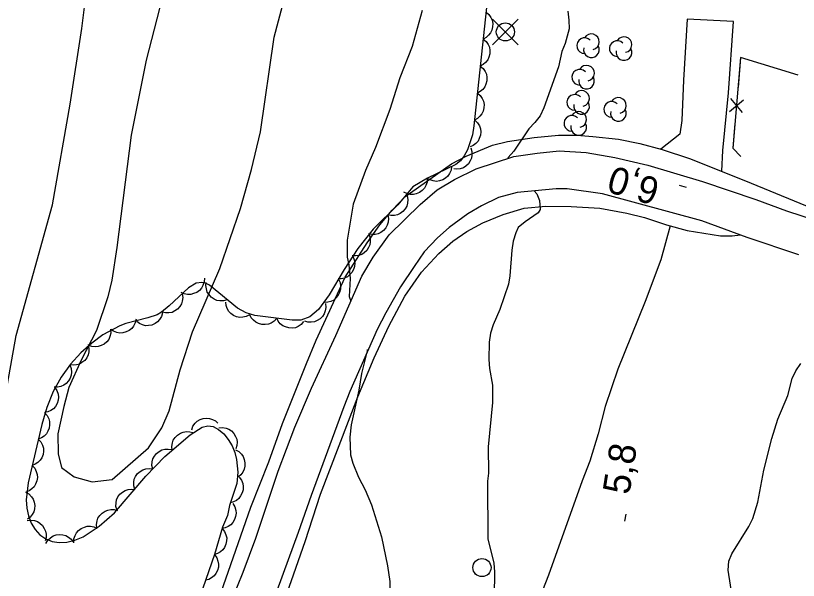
# Model space of a CAD drawing. Extents: x 282461 to 284471, y 5554090 to 5557646.
# Drawn here: x 283430.5 to 283517.1, y 5554920.6 to 5554983 of the extents above; entities that cross this region are included whole.
import ezdxf

# ---------------------------------------------------------------- set-up
doc = ezdxf.new("R2010")
doc.units = 0
for name, color, linetype in [('Niveau 1', 7, 'Continuous'), ('Niveau 19', 7, 'Continuous'), ('Niveau 2', 7, 'Continuous'), ('Niveau 21', 7, 'Continuous'), ('Niveau 22', 7, 'Continuous'), ('Niveau 3', 7, 'Continuous'), ('Niveau 36', 7, 'Continuous'), ('Niveau 37', 7, 'Continuous'), ('Niveau 44', 7, 'Continuous')]:
    doc.layers.add(name, color=color, linetype=linetype)

msp = doc.modelspace()

# ---------------------------------------------------------------- linework, layer by layer
at = {"layer": 'Niveau 1'}
for points in [[(283491.56, 5554983.49), (283491.69, 5554982.5), (283491.7, 5554981.52), (283491.26, 5554979.89), (283490.92, 5554979.02), (283490.53, 5554977.33), (283488.9, 5554972.8), (283488.5, 5554971.92), (283487.93, 5554971.17), (283487.24, 5554970.46), (283485.59, 5554968.01), (283484.96, 5554967.31), (283484.88, 5554967.16)], [(283487.85, 5554963.62), (283488.14, 5554963.29), (283488.44, 5554962.54), (283488.51, 5554961.55), (283488.28, 5554961.2), (283486.84, 5554960.2), (283486.09, 5554959.56), (283485.81, 5554958.98), (283485.53, 5554958.05), (283485.37, 5554957.06), (283485.17, 5554954.22), (283485, 5554953.29), (283484.05, 5554950.5), (283483.31, 5554948.81), (283483.03, 5554947.88), (283482.87, 5554946.9), (283482.83, 5554944.98), (283482.9, 5554944), (283483.22, 5554942.15), (283483.24, 5554940.24), (283482.77, 5554935.31), (283482.81, 5554932.41), (283482.7, 5554931.54), (283482.72, 5554925.17), (283483.39, 5554922.45), (283483.46, 5554921.52), (283483.43, 5554918.8)], [(283509.74, 5554918.86), (283509.3, 5554921.7), (283509.35, 5554922.68), (283509.68, 5554923.5), (283511.57, 5554926.53), (283512.02, 5554927.4), (283512.58, 5554929.2), (283513.24, 5554932.74), (283514.13, 5554936.23), (283514.8, 5554938.38), (283515.87, 5554941), (283516.37, 5554942.86), (283516.77, 5554943.73), (283517.34, 5554944.54)]]:
    msp.add_lwpolyline(points, dxfattribs=at)
at = {"layer": 'Niveau 19'}
msp.add_lwpolyline([(283508.58, 5554965.8), (283508.69, 5554968.08), (283509.33, 5554974.46), (283509.88, 5554982.34), (283504.77, 5554982.58), (283504.36, 5554975.86), (283504.18, 5554971.4), (283503.94, 5554969.89), (283501.86, 5554968.21)], dxfattribs=at)
at = {"layer": 'Niveau 2'}
for points in [[(283428.84, 5554937.89), (283430.58, 5554947.64), (283434.6, 5554962.06), (283436.56, 5554973.21), (283437.85, 5554981.57), (283438.49, 5554986.91), (283440.02, 5554994.58), (283441.12, 5555000.62), (283444.68, 5555013.88), (283446.71, 5555019.23), (283450.1, 5555026.92), (283452.13, 5555032.74), (283455.26, 5555043.44), (283455.92, 5555046.46), (283458.16, 5555053.68), (283461.99, 5555064.39)], [(283449.39, 5554995.38), (283444.94, 5554978.05), (283443.29, 5554969.79), (283441.69, 5554957.36), (283441.15, 5554953.75), (283440.71, 5554951.89), (283439.47, 5554948.17), (283437.77, 5554944.9)], [(283437.77, 5554944.9), (283436.41, 5554941.87), (283435.85, 5554939.78), (283435.19, 5554936.76), (283435.21, 5554934.55), (283435.58, 5554933.05), (283436.99, 5554932.01), (283438.97, 5554931.45), (283441.18, 5554931.7), (283445.21, 5554935.22), (283446.69, 5554937.44), (283447.48, 5554939.3), (283448.71, 5554943.84), (283450.06, 5554948.03), (283453.11, 5554955.02), (283455.36, 5554961.66), (283456.59, 5554965.97), (283457.59, 5554970.15), (283459.1, 5554980.61), (283460.21, 5554984.8)], [(283475.48, 5554983.55), (283474.37, 5554979.59), (283473.01, 5554976.1), (283471.89, 5554972.61), (283470.31, 5554968.42), (283469.18, 5554965.86), (283467.83, 5554962.13), (283467.18, 5554958.18), (283467.17, 5554956.3), (283467.36, 5554955.43), (283467.49, 5554953.92), (283467.4, 5554951.95), (283467.58, 5554951.44)], [(283469.37, 5554946.09), (283469.38, 5554945.94), (283468.77, 5554943.44), (283468.45, 5554941.58), (283467.62, 5554937.75), (283467.46, 5554936.41), (283467.54, 5554934.44), (283467.79, 5554933.52), (283468.44, 5554931.96), (283469.16, 5554930.57), (283469.87, 5554928.9), (283470.96, 5554925.37), (283471.64, 5554922.18), (283471.89, 5554920.45), (283471.92, 5554918.19), (283471.6, 5554915.28), (283470.94, 5554912.21), (283470.8, 5554910.14)]]:
    msp.add_lwpolyline(points, dxfattribs=at)
at = {"layer": 'Niveau 21'}
for points in [[(283451.28, 5554913.64), (283456.53, 5554928.64), (283458.5, 5554933.65), (283460.02, 5554937.89), (283462.67, 5554944.53), (283463.75, 5554947.12), (283466.96, 5554954.08), (283469.39, 5554957.87), (283470.78, 5554959.86), (283472.14, 5554961.5), (283473.53, 5554962.94), (283478.69, 5554966.62), (283480.32, 5554967.45), (283483.24, 5554968.67), (283484.91, 5554969.09), (283487.84, 5554969.5), (283490.52, 5554969.76), (283492.56, 5554969.76), (283494.33, 5554969.63), (283497.18, 5554969.34), (283499.51, 5554968.85), (283502, 5554968.18), (283505.02, 5554967.2), (283511.22, 5554964.73), (283519.9, 5554961.14)], [(283454.42, 5554918.36), (283455.68, 5554921.48), (283457.06, 5554925.23), (283459.56, 5554932.65), (283461.39, 5554937.51), (283463.23, 5554941.79), (283465.9, 5554947.63), (283468.78, 5554954.19), (283470.06, 5554956.29), (283471.83, 5554958.77), (283475.24, 5554962.12), (283477.11, 5554963.73), (283479.03, 5554964.88), (283481.44, 5554966.04), (283485.61, 5554967.4), (283488.19, 5554967.8), (283490.59, 5554968.03), (283493.61, 5554967.86), (283496.77, 5554967.29), (283500.4, 5554966.46), (283506.44, 5554964.64), (283512.36, 5554962.66), (283515.73, 5554961.41), (283529.41, 5554956.95)], [(283517.11, 5554956.53), (283511.41, 5554958.48), (283506.39, 5554960.32), (283495.39, 5554963.28), (283491.48, 5554963.84), (283490.29, 5554963.85), (283485.96, 5554963.45), (283483.89, 5554962.9), (283482.01, 5554961.98), (283480.52, 5554961.09), (283478.46, 5554959.56), (283477.15, 5554958.42), (283475.69, 5554956.89), (283474.56, 5554955.26), (283473.06, 5554953.01), (283471.44, 5554950.15), (283470.49, 5554948.29), (283467.46, 5554941.44), (283466.81, 5554939.73), (283463.18, 5554929.95), (283461.77, 5554925.85), (283458.29, 5554916.39)], [(283456.73, 5554908.34), (283462.54, 5554924.87), (283464.22, 5554930.1), (283468.35, 5554940.84), (283470.16, 5554945.15), (283471.76, 5554948.65), (283473.53, 5554951.97), (283475.4, 5554954.63), (283477.31, 5554956.68), (283478.85, 5554958.06), (283480.39, 5554959.12), (283482.18, 5554960.09), (283484.43, 5554961.02), (283486.75, 5554961.71), (283489.14, 5554961.94), (283491.93, 5554961.9), (283495.1, 5554961.7), (283498.09, 5554961.16), (283500.05, 5554960.69), (283502.47, 5554959.87), (283504.77, 5554959.23), (283508.43, 5554958.65), (283509.74, 5554958.64), (283510.66, 5554958.77)]]:
    msp.add_lwpolyline(points, dxfattribs=at)
at = {"layer": 'Niveau 22'}
msp.add_lwpolyline([(283502.87, 5554959.76), (283501.86, 5554955.98), (283500.11, 5554951.39), (283497.09, 5554943.9), (283495.69, 5554939.77), (283494.91, 5554936.75), (283493.99, 5554933.73), (283493.15, 5554931.58), (283489.44, 5554921.14), (283487.04, 5554915.03), (283485.83, 5554912.28), (283483.49, 5554905.88), (283481.09, 5554899.64), (283477.06, 5554887.26), (283475.82, 5554884.03)], dxfattribs=at)
at = {"layer": 'Niveau 3'}
for p, q in [((283504.67, 5554963.99), (283503.9, 5554964.22)), ((283497.88, 5554927.1), (283498, 5554927.89))]:
    msp.add_line(p, q, dxfattribs=at)
at = {"layer": 'Niveau 36'}
for p, q in [((283486.06, 5554979.77), (283483.24, 5554982.59)), ((283483.24, 5554979.77), (283486.06, 5554982.59))]:
    msp.add_line(p, q, dxfattribs=at)
for centre in [(283484.659, 5554981.191), (283482.075, 5554921.973)]:
    msp.add_circle(centre, 1, dxfattribs=at)
at = {"layer": 'Niveau 37'}
for p, q in [((283509.44, 5554972.39), (283510.97, 5554973.68)), ((283509.56, 5554973.81), (283510.85, 5554972.27))]:
    msp.add_line(p, q, dxfattribs=at)
for points in [[(283517.02, 5554976.4), (283510.67, 5554978.37), (283509.8, 5554968.35), (283510.68, 5554967.43)], [(283517.02, 5554976.4), (283510.67, 5554978.37), (283510.38, 5554975.03)], [(283510.03, 5554971.05), (283509.8, 5554968.35), (283510.68, 5554967.43)]]:
    msp.add_lwpolyline(points, dxfattribs=at)
at = {"layer": 'Niveau 44'}
for points in [[(283482.65, 5554984.58), (283481.18, 5554970.8), (283481.01, 5554969.81), (283480.48, 5554968.15), (283480.12, 5554967.48), (283479.69, 5554966.95), (283479.19, 5554966.54), (283476.05, 5554965.01), (283474.44, 5554964.05), (283472.77, 5554962.06), (283470.05, 5554959.37), (283468.34, 5554957.23), (283466.84, 5554954.93), (283465.18, 5554952.14), (283463.99, 5554950.49), (283463.05, 5554949.69), (283462.03, 5554949.33), (283461.09, 5554949.32), (283456.98, 5554949.85), (283456, 5554950.13), (283455.03, 5554950.64), (283451.95, 5554953.2), (283451.51, 5554953.4), (283451.11, 5554953.48), (283450.46, 5554953.4), (283449.64, 5554952.9), (283447.5, 5554950.92), (283446.63, 5554950.21), (283446.15, 5554949.93), (283445.13, 5554949.58), (283442.7, 5554948.97), (283442.05, 5554948.71), (283440.17, 5554947.69), (283438.93, 5554946.78), (283437.71, 5554945.72), (283436.57, 5554944.46), (283435.57, 5554943.04), (283434.67, 5554941.43), (283433.96, 5554939.66), (283433.4, 5554937.8), (283431.9, 5554931.36), (283431.68, 5554929.47), (283431.75, 5554928.55), (283431.94, 5554927.68), (283432.25, 5554926.89), (283432.68, 5554926.18), (283433.21, 5554925.59), (283433.84, 5554925.14), (283434.56, 5554924.85), (283435.34, 5554924.73), (283436.19, 5554924.78), (283437.07, 5554924.99), (283437.98, 5554925.38), (283439.77, 5554926.54), (283441.46, 5554928.02), (283444.93, 5554932.07), (283447.03, 5554934.27), (283449.83, 5554936.65), (283451.14, 5554937.5), (283451.78, 5554937.66), (283452.37, 5554937.56), (283452.96, 5554937.25), (283453.52, 5554936.77), (283454.03, 5554936.15), (283454.44, 5554935.45), (283454.74, 5554934.7), (283454.93, 5554933.92), (283455.08, 5554932.54), (283454.98, 5554931.26), (283454.15, 5554928.84), (283453.94, 5554927.72), (283453.38, 5554926.43), (283452.5, 5554923.42), (283451.21, 5554919.71)], [(283482.52, 5554983.38), (283482.84, 5554983.11), (283483.06, 5554982.77), (283483.2, 5554982.47), (283483.26, 5554982.12), (283483.25, 5554981.75), (283483.15, 5554981.38), (283483.03, 5554981.08), (283482.8, 5554980.81), (283482.52, 5554980.56), (283482.2, 5554980.4)], [(283482.2, 5554980.4), (283482.52, 5554980.13), (283482.74, 5554979.78), (283482.89, 5554979.49), (283482.94, 5554979.14), (283482.93, 5554978.77), (283482.83, 5554978.4), (283482.71, 5554978.1), (283482.48, 5554977.82), (283482.2, 5554977.58), (283481.89, 5554977.41)], [(283481.89, 5554977.41), (283482.2, 5554977.14), (283482.43, 5554976.8), (283482.57, 5554976.5), (283482.62, 5554976.15), (283482.61, 5554975.78), (283482.51, 5554975.41), (283482.39, 5554975.11), (283482.16, 5554974.84), (283481.88, 5554974.6), (283481.57, 5554974.43)], [(283481.57, 5554974.43), (283481.89, 5554974.16), (283482.11, 5554973.82), (283482.25, 5554973.52), (283482.3, 5554973.17), (283482.29, 5554972.8), (283482.19, 5554972.43), (283482.07, 5554972.13), (283481.85, 5554971.86), (283481.57, 5554971.61), (283481.25, 5554971.44)], [(283481.29, 5554971.44), (283481.59, 5554971.15), (283481.79, 5554970.79), (283481.91, 5554970.48), (283481.94, 5554970.13), (283481.91, 5554969.77), (283481.78, 5554969.4), (283481.64, 5554969.11), (283481.4, 5554968.85), (283481.11, 5554968.63), (283480.78, 5554968.48)], [(283480.85, 5554968.37), (283480.97, 5554967.97), (283480.97, 5554967.57), (283480.92, 5554967.24), (283480.78, 5554966.92), (283480.57, 5554966.61), (283480.28, 5554966.36), (283480.02, 5554966.17), (283479.68, 5554966.07), (283479.31, 5554966.01), (283478.95, 5554966.04)], [(283478.72, 5554966.31), (283478.66, 5554965.9), (283478.49, 5554965.53), (283478.31, 5554965.25), (283478.05, 5554965.02), (283477.73, 5554964.83), (283477.36, 5554964.72), (283477.04, 5554964.66), (283476.69, 5554964.71), (283476.34, 5554964.82), (283476.02, 5554965)], [(283476.03, 5554965), (283476, 5554964.58), (283475.86, 5554964.2), (283475.71, 5554963.9), (283475.46, 5554963.65), (283475.16, 5554963.44), (283474.8, 5554963.3), (283474.49, 5554963.21), (283474.14, 5554963.23), (283473.77, 5554963.31), (283473.45, 5554963.46)], [(283473.8, 5554963.07), (283473.87, 5554962.66), (283473.83, 5554962.26), (283473.75, 5554961.94), (283473.57, 5554961.64), (283473.33, 5554961.35), (283473.02, 5554961.13), (283472.73, 5554960.97), (283472.39, 5554960.91), (283472.01, 5554960.89), (283471.66, 5554960.96)], [(283471.66, 5554960.96), (283471.74, 5554960.55), (283471.69, 5554960.15), (283471.61, 5554959.83), (283471.44, 5554959.52), (283471.2, 5554959.24), (283470.88, 5554959.02), (283470.6, 5554958.86), (283470.25, 5554958.8), (283469.88, 5554958.78), (283469.53, 5554958.85)], [(283469.59, 5554958.8), (283469.72, 5554958.4), (283469.72, 5554957.99), (283469.68, 5554957.66), (283469.53, 5554957.34), (283469.33, 5554957.03), (283469.04, 5554956.78), (283468.78, 5554956.59), (283468.44, 5554956.48), (283468.08, 5554956.42), (283467.72, 5554956.45)], [(283467.8, 5554956.39), (283467.96, 5554956.01), (283468, 5554955.61), (283467.99, 5554955.27), (283467.88, 5554954.94), (283467.7, 5554954.61), (283467.44, 5554954.33), (283467.2, 5554954.12), (283466.88, 5554953.98), (283466.52, 5554953.89), (283466.16, 5554953.88)], [(283451.39, 5554953.97), (283451.37, 5554953.55), (283451.23, 5554953.17), (283451.08, 5554952.87), (283450.84, 5554952.62), (283450.54, 5554952.4), (283450.18, 5554952.26), (283449.87, 5554952.17), (283449.52, 5554952.18), (283449.15, 5554952.25), (283448.83, 5554952.4)], [(283453.9, 5554951.58), (283453.5, 5554951.46), (283453.1, 5554951.46), (283452.77, 5554951.51), (283452.45, 5554951.66), (283452.15, 5554951.87), (283451.9, 5554952.16), (283451.71, 5554952.43), (283451.61, 5554952.77), (283451.56, 5554953.14), (283451.6, 5554953.49)], [(283466.2, 5554953.85), (283466.38, 5554953.48), (283466.44, 5554953.07), (283466.44, 5554952.74), (283466.34, 5554952.4), (283466.18, 5554952.07), (283465.93, 5554951.78), (283465.7, 5554951.55), (283465.38, 5554951.4), (283465.02, 5554951.3), (283464.66, 5554951.27)], [(283448.94, 5554952.25), (283449, 5554951.84), (283448.94, 5554951.44), (283448.85, 5554951.12), (283448.67, 5554950.82), (283448.42, 5554950.55), (283448.1, 5554950.34), (283447.81, 5554950.19), (283447.46, 5554950.13), (283447.09, 5554950.13), (283446.74, 5554950.21)], [(283456.39, 5554949.92), (283456.02, 5554949.73), (283455.62, 5554949.65), (283455.29, 5554949.63), (283454.95, 5554949.7), (283454.61, 5554949.85), (283454.31, 5554950.08), (283454.07, 5554950.3), (283453.9, 5554950.61), (283453.78, 5554950.96), (283453.74, 5554951.32)], [(283464.77, 5554951.16), (283464.82, 5554950.74), (283464.74, 5554950.34), (283464.64, 5554950.03), (283464.44, 5554949.74), (283464.18, 5554949.47), (283463.85, 5554949.28), (283463.55, 5554949.14), (283463.2, 5554949.1), (283462.83, 5554949.11), (283462.49, 5554949.21)], [(283446.75, 5554950.14), (283446.64, 5554949.73), (283446.43, 5554949.39), (283446.22, 5554949.13), (283445.93, 5554948.94), (283445.59, 5554948.79), (283445.21, 5554948.73), (283444.88, 5554948.71), (283444.54, 5554948.8), (283444.2, 5554948.95), (283443.92, 5554949.16)], [(283443.83, 5554949.42), (283443.74, 5554949.02), (283443.55, 5554948.66), (283443.35, 5554948.4), (283443.07, 5554948.19), (283442.74, 5554948.02), (283442.36, 5554947.94), (283442.04, 5554947.9), (283441.69, 5554947.97), (283441.35, 5554948.11), (283441.05, 5554948.31)], [(283459.38, 5554949.54), (283459.11, 5554949.23), (283458.76, 5554949.01), (283458.46, 5554948.88), (283458.11, 5554948.83), (283457.74, 5554948.85), (283457.38, 5554948.96), (283457.07, 5554949.09), (283456.81, 5554949.32), (283456.57, 5554949.6), (283456.41, 5554949.92)], [(283462.36, 5554949.16), (283462.08, 5554948.84), (283461.74, 5554948.63), (283461.44, 5554948.49), (283461.09, 5554948.45), (283460.72, 5554948.46), (283460.35, 5554948.58), (283460.05, 5554948.7), (283459.78, 5554948.93), (283459.55, 5554949.22), (283459.38, 5554949.54)], [(283441.02, 5554948.32), (283441.04, 5554947.9), (283440.94, 5554947.51), (283440.81, 5554947.2), (283440.59, 5554946.93), (283440.31, 5554946.68), (283439.97, 5554946.51), (283439.66, 5554946.4), (283439.31, 5554946.38), (283438.94, 5554946.42), (283438.6, 5554946.54)], [(283438.52, 5554946.62), (283438.62, 5554946.21), (283438.6, 5554945.81), (283438.54, 5554945.48), (283438.38, 5554945.17), (283438.15, 5554944.87), (283437.85, 5554944.64), (283437.58, 5554944.46), (283437.24, 5554944.38), (283436.87, 5554944.34), (283436.51, 5554944.39)], [(283436.52, 5554944.39), (283436.67, 5554944), (283436.69, 5554943.59), (283436.67, 5554943.26), (283436.55, 5554942.93), (283436.36, 5554942.61), (283436.09, 5554942.34), (283435.84, 5554942.13), (283435.51, 5554942), (283435.15, 5554941.93), (283434.79, 5554941.93)], [(283434.85, 5554941.88), (283435.09, 5554941.54), (283435.21, 5554941.15), (283435.26, 5554940.82), (283435.22, 5554940.47), (283435.11, 5554940.12), (283434.91, 5554939.79), (283434.71, 5554939.53), (283434.42, 5554939.33), (283434.09, 5554939.18), (283433.73, 5554939.1)], [(283433.7, 5554939.1), (283433.99, 5554938.8), (283434.17, 5554938.43), (283434.27, 5554938.12), (283434.28, 5554937.76), (283434.23, 5554937.4), (283434.08, 5554937.05), (283433.92, 5554936.76), (283433.67, 5554936.52), (283433.36, 5554936.31), (283433.02, 5554936.18)], [(283449.98, 5554937.21), (283450.12, 5554937.6), (283450.37, 5554937.93), (283450.6, 5554938.16), (283450.91, 5554938.33), (283451.26, 5554938.45), (283451.64, 5554938.48), (283451.96, 5554938.47), (283452.3, 5554938.36), (283452.62, 5554938.18), (283452.89, 5554937.94)], [(283447.82, 5554934.94), (283447.77, 5554935.36), (283447.85, 5554935.76), (283447.95, 5554936.07), (283448.15, 5554936.36), (283448.41, 5554936.62), (283448.74, 5554936.82), (283449.04, 5554936.96), (283449.39, 5554937), (283449.76, 5554936.98), (283450.11, 5554936.89)], [(283452.97, 5554937.43), (283453.39, 5554937.47), (283453.79, 5554937.39), (283454.1, 5554937.28), (283454.39, 5554937.08), (283454.65, 5554936.81), (283454.84, 5554936.48), (283454.97, 5554936.18), (283455, 5554935.83), (283454.98, 5554935.46), (283454.88, 5554935.12)], [(283433.02, 5554936.18), (283433.31, 5554935.87), (283433.48, 5554935.51), (283433.59, 5554935.19), (283433.6, 5554934.84), (283433.55, 5554934.48), (283433.4, 5554934.12), (283433.24, 5554933.84), (283432.99, 5554933.59), (283432.68, 5554933.39), (283432.34, 5554933.26)], [(283445.67, 5554932.85), (283445.59, 5554933.26), (283445.62, 5554933.66), (283445.69, 5554933.99), (283445.86, 5554934.29), (283446.09, 5554934.58), (283446.4, 5554934.81), (283446.68, 5554934.98), (283447.02, 5554935.06), (283447.39, 5554935.08), (283447.75, 5554935.02)], [(283454.81, 5554935), (283455.18, 5554934.8), (283455.47, 5554934.51), (283455.67, 5554934.25), (283455.8, 5554933.92), (283455.87, 5554933.56), (283455.85, 5554933.18), (283455.79, 5554932.86), (283455.63, 5554932.54), (283455.41, 5554932.24), (283455.14, 5554932.01)], [(283432.34, 5554933.26), (283432.63, 5554932.95), (283432.8, 5554932.58), (283432.91, 5554932.27), (283432.92, 5554931.92), (283432.87, 5554931.55), (283432.72, 5554931.2), (283432.56, 5554930.91), (283432.3, 5554930.67), (283432, 5554930.46), (283431.66, 5554930.33)], [(283443.68, 5554930.61), (283443.57, 5554931.01), (283443.58, 5554931.42), (283443.63, 5554931.74), (283443.78, 5554932.06), (283444, 5554932.36), (283444.29, 5554932.61), (283444.57, 5554932.79), (283444.9, 5554932.89), (283445.27, 5554932.93), (283445.63, 5554932.89)], [(283455.22, 5554931.97), (283455.48, 5554931.64), (283455.62, 5554931.26), (283455.69, 5554930.93), (283455.66, 5554930.58), (283455.57, 5554930.22), (283455.39, 5554929.89), (283455.2, 5554929.62), (283454.92, 5554929.4), (283454.6, 5554929.23), (283454.25, 5554929.13)], [(283431.62, 5554930.32), (283431.98, 5554930.11), (283432.26, 5554929.81), (283432.45, 5554929.54), (283432.57, 5554929.21), (283432.63, 5554928.85), (283432.59, 5554928.47), (283432.53, 5554928.15), (283432.36, 5554927.84), (283432.13, 5554927.55), (283431.84, 5554927.32)], [(283441.73, 5554928.33), (283441.61, 5554928.73), (283441.63, 5554929.14), (283441.68, 5554929.47), (283441.83, 5554929.78), (283442.05, 5554930.08), (283442.34, 5554930.33), (283442.61, 5554930.51), (283442.95, 5554930.61), (283443.32, 5554930.65), (283443.68, 5554930.61)], [(283439.51, 5554926.31), (283439.46, 5554926.73), (283439.53, 5554927.13), (283439.62, 5554927.44), (283439.82, 5554927.73), (283440.08, 5554928), (283440.4, 5554928.2), (283440.7, 5554928.34), (283441.05, 5554928.39), (283441.42, 5554928.38), (283441.77, 5554928.29)], [(283454.52, 5554929.05), (283454.74, 5554928.7), (283454.85, 5554928.3), (283454.9, 5554927.98), (283454.84, 5554927.63), (283454.73, 5554927.28), (283454.52, 5554926.96), (283454.31, 5554926.7), (283454.02, 5554926.51), (283453.68, 5554926.36), (283453.32, 5554926.3)], [(283431.79, 5554927.18), (283432.2, 5554927.23), (283432.6, 5554927.17), (283432.92, 5554927.07), (283433.21, 5554926.88), (283433.48, 5554926.63), (283433.69, 5554926.31), (283433.83, 5554926.01), (283433.88, 5554925.66), (283433.88, 5554925.29), (283433.79, 5554924.94)], [(283436.96, 5554924.72), (283436.97, 5554925.14), (283437.09, 5554925.52), (283437.24, 5554925.82), (283437.47, 5554926.08), (283437.77, 5554926.31), (283438.12, 5554926.46), (283438.43, 5554926.56), (283438.78, 5554926.56), (283439.15, 5554926.49), (283439.48, 5554926.35)], [(283453.34, 5554926.29), (283453.61, 5554925.97), (283453.76, 5554925.59), (283453.85, 5554925.27), (283453.84, 5554924.92), (283453.77, 5554924.56), (283453.6, 5554924.21), (283453.43, 5554923.94), (283453.16, 5554923.71), (283452.84, 5554923.52), (283452.5, 5554923.41)], [(283433.87, 5554924.64), (283434.09, 5554925), (283434.39, 5554925.28), (283434.66, 5554925.47), (283434.99, 5554925.58), (283435.36, 5554925.63), (283435.74, 5554925.59), (283436.06, 5554925.52), (283436.36, 5554925.34), (283436.65, 5554925.11), (283436.87, 5554924.82)], [(283452.5, 5554923.41), (283452.75, 5554923.07), (283452.88, 5554922.69), (283452.95, 5554922.37), (283452.93, 5554922.02), (283452.84, 5554921.66), (283452.65, 5554921.32), (283452.47, 5554921.06), (283452.19, 5554920.84), (283451.86, 5554920.67), (283451.51, 5554920.57)]]:
    msp.add_lwpolyline(points, dxfattribs=at)
for centre, start, end in [((283493.424, 5554979.661), 44.11537, 269.80396), ((283494.171, 5554980.095), 282.26917, 149.72625), ((283497.773, 5554979.781), 282.26917, 149.72625), ((283494.171, 5554979.226), 166.93686, 29.62122), ((283497.026, 5554979.347), 44.11537, 269.80396), ((283497.773, 5554978.912), 166.93686, 29.62122), ((283492.884, 5554976.181), 44.11537, 269.80396), ((283493.631, 5554976.616), 282.26917, 149.72625), ((283493.631, 5554975.746), 166.93686, 29.62122), ((283492.336, 5554973.396), 44.11537, 269.80396), ((283493.084, 5554973.831), 282.26917, 149.72625), ((283493.084, 5554972.962), 166.93686, 29.62122), ((283496.408, 5554972.623), 44.11537, 269.80396), ((283497.155, 5554973.058), 282.26917, 149.72625), ((283497.155, 5554972.189), 166.93686, 29.62122), ((283492.015, 5554971.077), 44.11537, 269.80396), ((283492.762, 5554971.512), 282.26917, 149.72625), ((283492.762, 5554970.642), 166.93686, 29.62122)]:
    msp.add_arc(centre, 0.869, start, end, dxfattribs=at)

# ---------------------------------------------------------------- texts
at = {"layer": 'Niveau 3'}
for s, rotation, p in [('6,0  ', 163.4128, (283501.92, 5554964.85)), ('5,8  ', 81.09575, (283498.36, 5554929.94))]:
    msp.add_text(s, height=3, rotation=rotation, dxfattribs=at).set_placement(p)

doc.saveas('drawing.dxf')
